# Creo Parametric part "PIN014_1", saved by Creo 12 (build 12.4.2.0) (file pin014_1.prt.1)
Units: Custom; MM, KILOGRAM, SECS

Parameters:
  PTC_WM_ITERATION = "0"
  PTC_WM_VERSION = "-.0"
  PTC_WM_LIFECYCLE_STATE = "In Work"
  PTC_WM_LIFECYCLE = "MO_CADDocument"
  PTC_WM_CREATED_BY = "Maximilian Roepper (Z0017RMS: MO)"
  PTC_WM_CREATED_ON = "18-Sep-26 11:36:42 AM"
  PTC_WM_MODIFIED_BY = "Maximilian Roepper (Z0017RMS: MO)"
  PTC_WM_MODIFIED_ON = "18-Sep-26 11:36:46 AM"
  PDMLINKNUMBER = "PDM000071455122"
  PTC_WM_NAME = "pin014_1.prt"
  PTC_WM_NUMBER = "PDM000071455122"

Other parameters: WEIGHT, WEIGHT_FACTOR, WEIGHT_ADD, _MASS_TEMP, _DIFF_TEMP, MC_ERRORS, SUPPLIER

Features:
  1. coordinate system
  2. datum plane "PRT_YZ"
  3. datum plane "PRT_XY"
  4. datum plane "PRT_XZ"
  5. coordinate system
  6. datum axis
  7. datum axis
  8. datum axis
  9. coordinate system
  10. imported feature

Other named items: PRT, SIEMENS_MO, DRW_VIEW_ORG, PRT_X, PRT_Y, PRT_Z, CS0, ROUGH_GROB

Layers: 00_STD_CSYS-KSYS, 01_STD_PLANES-EBENEN, 02_STD_AXES-ACHSEN, 03_STD_CSYS-KSYS, 24_IMPORT_FEAT-IMPORT_KE

Surfaces: 14 plane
